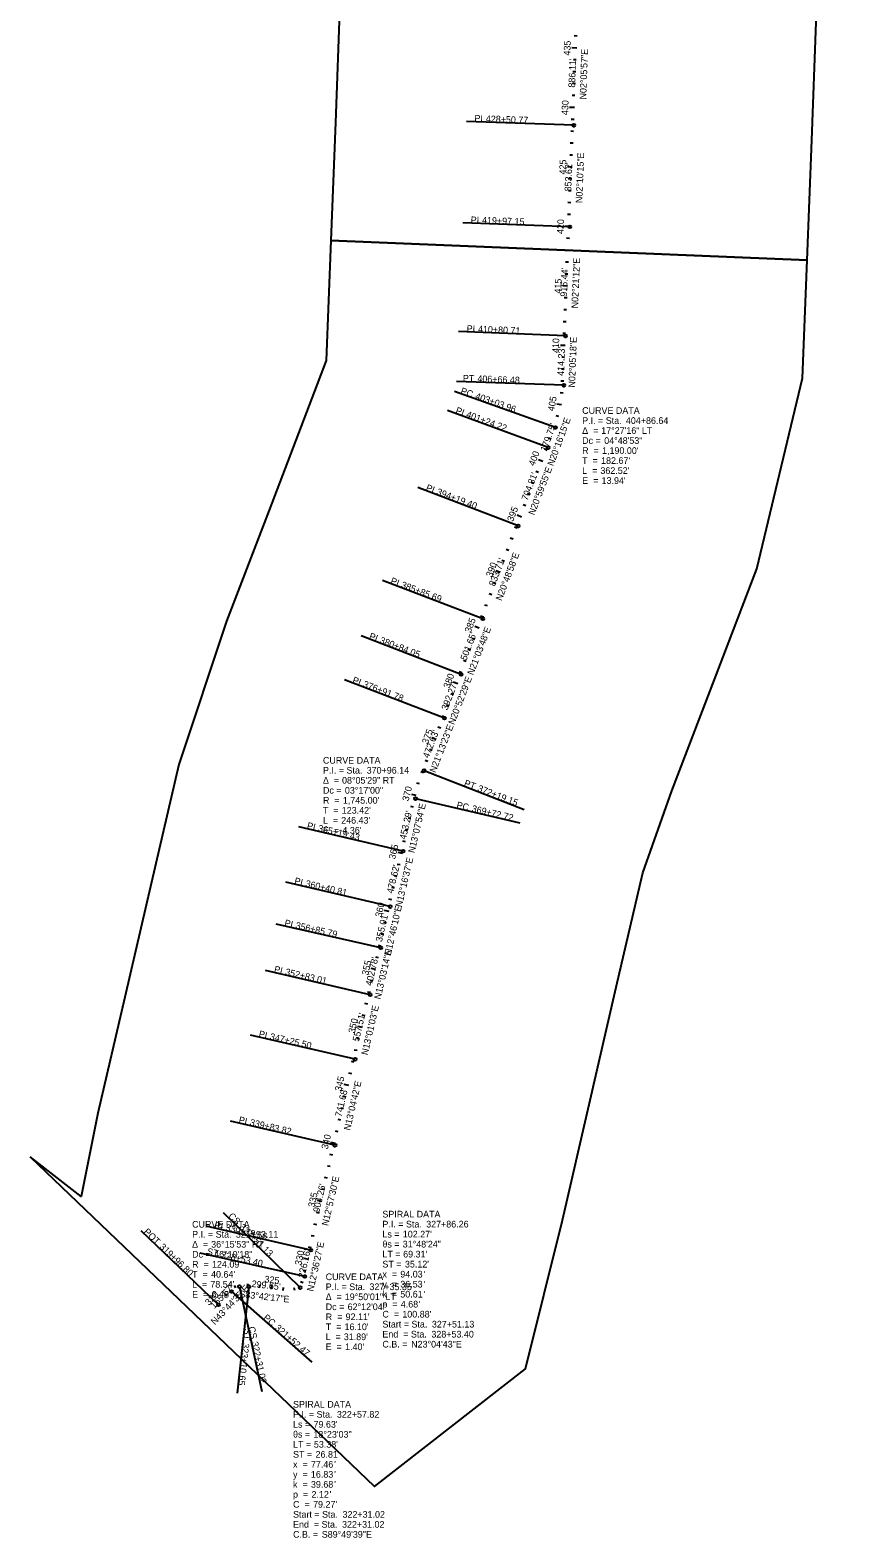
# Model space of a CAD drawing. Extents: x 1697889 to 1709091, y 242468 to 292801.
# Drawn here: x 1697889 to 1704792, y 242468 to 255128 of the extents above; entities that cross this region are included whole.
import ezdxf

# ---------------------------------------------------------------- set-up
doc = ezdxf.new("R2010")
doc.units = 0
for name, color, linetype in [('RD_P_Cells', 7, 'Continuous'), ('SC_Scratch1', 7, 'Continuous'), ('XS_P_Finished_Grade', 7, 'Continuous'), ('XS_P_Headwall', 7, 'Continuous'), ('XS_P_Pavt_Surface', 7, 'Continuous'), ('XS_P_Shoulder_Layers', 7, 'Continuous')]:
    doc.layers.add(name, color=color, linetype=linetype)

msp = doc.modelspace()

# ---------------------------------------------------------------- linework, layer by layer
at = {"layer": 'SC_Scratch1'}
for points in [[(1700412, 253361), (1704409, 253197), (1704447, 254203), (1704484, 255196), (1704524, 256197), (1704561, 257198), (1704600, 258191), (1704641, 259201), (1704677, 260205), (1704716, 261199), (1704754, 262194), (1704792, 263192), (1700795, 263352), (1700757, 262351), (1700719, 261347), (1700679, 260343), (1700644, 259348), (1700604, 258359), (1700564, 257354), (1700528, 256356), (1700487, 255359), (1700450, 254354)], [(1697889, 245666), (1700779, 242900), (1702046, 243888), (1702355, 245136), (1702580, 246108), (1702807, 247091), (1703031, 248053), (1703274, 248740), (1703632, 249675), (1703987, 250604), (1704369, 252207), (1704409, 253197), (1700412, 253361), (1700372, 252353), (1700252, 252037), (1699894, 251097), (1699537, 250165), (1699136, 248961), (1698906, 247975), (1698683, 247009), (1698457, 246033), (1698316, 245333)]]:
    msp.add_lwpolyline(points, close=True, dxfattribs=at)
at = {"layer": 'XS_P_Finished_Grade'}
for p, q in [((1702451, 254329), (1701551, 254362)), ((1702418, 253476), (1701519, 253510)), ((1702381, 252560), (1701482, 252597)), ((1702298, 251792), (1701450, 252093)), ((1702366, 252146), (1701466, 252179)), ((1702236, 251623), (1701391, 251935)), ((1701983, 250965), (1701143, 251288)), ((1701687, 250186), (1700846, 250506)), ((1701507, 249718), (1700667, 250041)), ((1701367, 249351), (1700526, 249672)), ((1701196, 248910), (1702035, 248585)), ((1701123, 248675), (1701999, 248471)), ((1701020, 248234), (1700143, 248438)), ((1700910, 247768), (1700034, 247975)), ((1700832, 247422), (1699954, 247621)), ((1700741, 247029), (1699864, 247233)), ((1700615, 246486), (1699738, 246689)), ((1700447, 245764), (1699571, 245967)), ((1700155, 244569), (1699511, 245198)), ((1699470, 244425), (1698820, 245047)), ((1700244, 244883), (1699367, 245084)), ((1700195, 244662), (1699317, 244858)), ((1699578, 244537), (1700254, 243944)), ((1699724, 244577), (1699626, 243682)), ((1699645, 244577), (1699834, 243697))]:
    msp.add_line(p, q, dxfattribs=at)
for centre in [(1702451, 254329), (1702418, 253476), (1702381, 252560), (1702366, 252146), (1702298, 251792), (1702236, 251623), (1701983, 250965), (1701687, 250186), (1701507, 249718), (1701367, 249351), (1701196, 248910), (1701123, 248675), (1701020, 248234), (1700910, 247768), (1700832, 247422), (1700741, 247029), (1700615, 246486), (1700447, 245764), (1700244, 244883), (1700195, 244662), (1699578, 244537), (1699645, 244577), (1699724, 244577), (1700155, 244569), (1699470, 244425)]:
    msp.add_circle(centre, 12, dxfattribs=at)
at = {"layer": 'XS_P_Headwall'}
for p, q in [((1702475, 254978), (1702435, 254979)), ((1702478, 255078), (1702454, 255079)), ((1702471, 254878), (1702447, 254879)), ((1702467, 254778), (1702443, 254779)), ((1702464, 254678), (1702440, 254679)), ((1702456, 254478), (1702416, 254480)), ((1702460, 254578), (1702436, 254579)), ((1702453, 254378), (1702429, 254379)), ((1702449, 254278), (1702425, 254279)), ((1702445, 254178), (1702421, 254179)), ((1702437, 253978), (1702397, 253980)), ((1702441, 254078), (1702417, 254079)), ((1702434, 253879), (1702410, 253879)), ((1702430, 253779), (1702406, 253779)), ((1702426, 253679), (1702402, 253680)), ((1702419, 253479), (1702379, 253480)), ((1702422, 253579), (1702398, 253580)), ((1702414, 253379), (1702390, 253380)), ((1702410, 253279), (1702386, 253280)), ((1702402, 253079), (1702378, 253080)), ((1702406, 253179), (1702382, 253180)), ((1702398, 252979), (1702358, 252981)), ((1702394, 252879), (1702370, 252880)), ((1702390, 252779), (1702366, 252780)), ((1702382, 252580), (1702358, 252581)), ((1702386, 252679), (1702362, 252680)), ((1702378, 252480), (1702338, 252481)), ((1702374, 252380), (1702350, 252381)), ((1702371, 252280), (1702347, 252281)), ((1702361, 252080), (1702337, 252082)), ((1702367, 252180), (1702343, 252181)), ((1702348, 251981), (1702309, 251988)), ((1702326, 251883), (1702303, 251890)), ((1702262, 251694), (1702239, 251702)), ((1702297, 251788), (1702274, 251796)), ((1702227, 251600), (1702205, 251609)), ((1702191, 251507), (1702154, 251521)), ((1702119, 251320), (1702097, 251329)), ((1702155, 251414), (1702133, 251422)), ((1702084, 251227), (1702061, 251236)), ((1702012, 251040), (1701975, 251055)), ((1702048, 251134), (1702025, 251142)), ((1701976, 250947), (1701954, 250955)), ((1701941, 250853), (1701918, 250862)), ((1701870, 250666), (1701847, 250675)), ((1701905, 250760), (1701883, 250768)), ((1701834, 250573), (1701797, 250587)), ((1701798, 250480), (1701776, 250488)), ((1701727, 250293), (1701705, 250301)), ((1701763, 250386), (1701741, 250395)), ((1701692, 250199), (1701669, 250208)), ((1701656, 250106), (1701619, 250120)), ((1701584, 249919), (1701562, 249928)), ((1701620, 250012), (1701598, 250021)), ((1701548, 249826), (1701526, 249834)), ((1701512, 249732), (1701490, 249741)), ((1701441, 249546), (1701418, 249554)), ((1701477, 249639), (1701439, 249653)), ((1701405, 249452), (1701383, 249461)), ((1701370, 249359), (1701347, 249367)), ((1701297, 249172), (1701260, 249187)), ((1701334, 249266), (1701311, 249274)), ((1701261, 249079), (1701239, 249088)), ((1701189, 248893), (1701166, 248901)), ((1701225, 248986), (1701203, 248995)), ((1701156, 248798), (1701133, 248805)), ((1701129, 248702), (1701091, 248711)), ((1701106, 248604), (1701083, 248610)), ((1701061, 248410), (1701038, 248415)), ((1701084, 248507), (1701060, 248512)), ((1701038, 248312), (1701015, 248318)), ((1701015, 248215), (1700977, 248224)), ((1700970, 248020), (1700946, 248026)), ((1700993, 248118), (1700969, 248123)), ((1700947, 247923), (1700923, 247928)), ((1700924, 247826), (1700900, 247831)), ((1700879, 247631), (1700855, 247636)), ((1700901, 247728), (1700862, 247737)), ((1700857, 247533), (1700833, 247538)), ((1700835, 247436), (1700811, 247441)), ((1700812, 247338), (1700789, 247344)), ((1700767, 247143), (1700744, 247149)), ((1700790, 247241), (1700751, 247250)), ((1700744, 247046), (1700721, 247051)), ((1700722, 246948), (1700698, 246954)), ((1700677, 246754), (1700638, 246763)), ((1700699, 246851), (1700676, 246856)), ((1700654, 246656), (1700631, 246662)), ((1700632, 246559), (1700608, 246564)), ((1700587, 246364), (1700563, 246369)), ((1700609, 246461), (1700586, 246467)), ((1700564, 246267), (1700525, 246276)), ((1700541, 246169), (1700518, 246175)), ((1700519, 246072), (1700495, 246077)), ((1700473, 245877), (1700450, 245882)), ((1700496, 245974), (1700473, 245980)), ((1700451, 245780), (1700412, 245789)), ((1700428, 245682), (1700405, 245687)), ((1700384, 245487), (1700360, 245493)), ((1700406, 245585), (1700383, 245590)), ((1700361, 245390), (1700338, 245395)), ((1700339, 245292), (1700300, 245301)), ((1700294, 245097), (1700270, 245103)), ((1700316, 245195), (1700293, 245200)), ((1700271, 245000), (1700248, 245005)), ((1700249, 244902), (1700226, 244908)), ((1700227, 244805), (1700188, 244814)), ((1699714, 244578), (1699716, 244602)), ((1699913, 244556), (1699917, 244596)), ((1700181, 244610), (1700158, 244619)), ((1700205, 244707), (1700182, 244713)), ((1699542, 244500), (1699524, 244516)), ((1699615, 244566), (1699604, 244588)), ((1699813, 244567), (1699816, 244591)), ((1700012, 244545), (1700015, 244569)), ((1700111, 244544), (1700105, 244567)), ((1699472, 244427), (1699444, 244455))]:
    msp.add_line(p, q, dxfattribs=at)

# ---------------------------------------------------------------- texts
at = {"layer": 'RD_P_Cells'}
for s, p in [('CURVE DATA', (1702521, 251906)), ('P.I. = Sta. ', (1702521, 251822)), ('404+86.64', (1702888, 251822)), ('Δ  = ', (1702521, 251738)), ('Dc = ', (1702521, 251654)), ('17°27\'16" LT', (1702681, 251738)), ('04°48\'53"', (1702706, 251654)), ('R  = ', (1702521, 251570)), ("1,190.00'", (1702688, 251570)), ('T  = ', (1702521, 251486)), ('L  = ', (1702521, 251402)), ("362.52'", (1702674, 251402)), ("182.67'", (1702680, 251486)), ('E  = ', (1702521, 251318)), ("13.94'", (1702684, 251318)), ('CURVE DATA', (1700346, 248969)), ('P.I. = Sta. ', (1700346, 248885)), ('370+96.14', (1700713, 248885)), ('Δ  = ', (1700346, 248801)), ('Dc = ', (1700346, 248717)), ('08°05\'29" RT', (1700506, 248801)), ('03°17\'00"', (1700530, 248717)), ('R  = ', (1700346, 248633)), ("1,745.00'", (1700513, 248633)), ('T  = ', (1700346, 248549)), ('L  = ', (1700346, 248465)), ("246.43'", (1700499, 248465)), ("123.42'", (1700504, 248549)), ('E  = ', (1700346, 248381)), ("4.36'", (1700509, 248381)), ('CURVE DATA', (1699248, 245073)), ('SPIRAL DATA', (1700845, 245158)), ('P.I. = Sta. ', (1700845, 245074)), ('327+86.26', (1701212, 245074)), ('P.I. = Sta. ', (1699248, 244989)), ('321+93.11', (1699615, 244989)), ('Ls = ', (1700845, 244990)), ("102.27'", (1701016, 244990)), ('Δ  = ', (1699248, 244905)), ('Dc = ', (1699248, 244821)), ('36°15\'53" RT', (1699408, 244905)), ('46°10\'18"', (1699433, 244821)), ('θs = ', (1700845, 244906)), ('LT = ', (1700845, 244822)), ('31°48\'24"', (1701015, 244906)), ("69.31'", (1701019, 244822)), ('R  = ', (1699248, 244737)), ("124.09'", (1699415, 244737)), ('ST = ', (1700845, 244738)), ("35.12'", (1701034, 244738)), ('T  = ', (1699248, 244653)), ('L  = ', (1699248, 244569)), ("78.54'", (1699401, 244569)), ("40.64'", (1699407, 244653)), ('CURVE DATA', (1700369, 244632)), ('P.I. = Sta. ', (1700369, 244548)), ('327+35.35', (1700736, 244548)), ('y  = ', (1700845, 244570)), ('x  = ', (1700845, 244654)), ('94.03', (1700995, 244654)), ('36.53', (1700995, 244570)), ("'", (1701190, 244654)), ("'", (1701190, 244570)), ('E  = ', (1699248, 244485)), ("6.48'", (1699411, 244485)), ('Δ  = ', (1700369, 244464)), ('19°50\'01" LT', (1700529, 244464)), ('k  = ', (1700845, 244486)), ('50.61', (1700995, 244486)), ("'", (1701190, 244486)), ('Dc = ', (1700369, 244380)), ('R  = ', (1700369, 244296)), ("92.11'", (1700536, 244296)), ('62°12\'04"', (1700553, 244380)), ('C  = ', (1700845, 244318)), ('p  = ', (1700845, 244402)), ('4.68', (1700999, 244402)), ("100.88'", (1701012, 244318)), ("'", (1701151, 244402)), ('T  = ', (1700369, 244212)), ("16.10'", (1700527, 244212)), ('Start = Sta. ', (1700845, 244234)), ('327+51.13', (1701260, 244234)), ('L  = ', (1700369, 244128)), ('E  = ', (1700369, 244044)), ("31.89'", (1700521, 244128)), ("1.40'", (1700532, 244044)), ('C.B. = ', (1700845, 244066)), ('End  = Sta. ', (1700845, 244150)), ('N23°04\'43"E', (1701086, 244066)), ('328+53.40', (1701256, 244150)), ('SPIRAL DATA', (1700095, 243561)), ('P.I. = Sta. ', (1700095, 243477)), ('322+57.82', (1700463, 243477)), ('θs = ', (1700095, 243309)), ('Ls = ', (1700095, 243393)), ("79.63'", (1700267, 243393)), ('18°23\'03"', (1700266, 243309)), ('LT = ', (1700095, 243225)), ("53.38'", (1700270, 243225)), ('x  = ', (1700095, 243057)), ('ST = ', (1700095, 243141)), ('77.46', (1700245, 243057)), ("26.81'", (1700284, 243141)), ("'", (1700441, 243057)), ('y  = ', (1700095, 242973)), ('16.83', (1700245, 242973)), ("'", (1700441, 242973)), ('k  = ', (1700095, 242889)), ('p  = ', (1700095, 242805)), ('39.68', (1700245, 242889)), ('2.12', (1700250, 242805)), ("'", (1700402, 242805)), ("'", (1700441, 242889)), ('C  = ', (1700095, 242721)), ("79.27'", (1700263, 242721)), ('Start = Sta. ', (1700095, 242637)), ('End  = Sta. ', (1700095, 242553)), ('322+31.02', (1700506, 242553)), ('322+31.02', (1700510, 242637)), ('C.B. = ', (1700095, 242469)), ('S89°49\'39"E', (1700336, 242469))]:
    msp.add_text(s, height=56, dxfattribs=at).set_placement(p)
at = {"layer": 'XS_P_Finished_Grade'}
for s, rotation, p in [('PI', 357.9007, (1701616, 254360)), ('428+50.77', 357.9007, (1701712, 254357)), ('PI', 357.8292, (1701585, 253508)), ('419+97.15', 357.8292, (1701680, 253505)), ('PI', 357.6465, (1701551, 252595)), ('410+80.71', 357.6465, (1701646, 252591)), ('PT', 357.9116, (1701519, 252178)), ('406+66.48', 357.9116, (1701641, 252174)), ('PC', 340.4571, (1701496, 252077)), ('403+03.96', 340.4571, (1701619, 252034)), ('PI', 339.7292, (1701454, 251913)), ('401+24.22', 339.7292, (1701543, 251880)), ('PI', 339.0014, (1701205, 251265)), ('394+19.40', 339.0014, (1701294, 251231)), ('PI', 339.184, (1700908, 250483)), ('385+85.69', 339.184, (1700997, 250449)), ('PI', 338.9367, (1700728, 250018)), ('380+84.05', 338.9367, (1700817, 249984)), ('PI', 339.1253, (1700588, 249649)), ('376+91.78', 339.1253, (1700677, 249615)), ('PT', 338.777, (1701525, 248784)), ('372+19.15', 338.777, (1701638, 248740)), ('PC', 346.8683, (1701463, 248597)), ('369+72.72', 346.8683, (1701590, 248567)), ('PI', 346.8683, (1700208, 248424)), ('365+19.43', 346.8683, (1700301, 248402)), ('PI', 346.7231, (1700102, 247960)), ('360+40.81', 346.7231, (1700195, 247938)), ('PI', 347.2306, (1700019, 247607)), ('356+85.79', 347.2306, (1700112, 247586)), ('PI', 346.9462, (1699932, 247218)), ('352+83.01', 346.9462, (1700025, 247196)), ('PI', 346.9824, (1699803, 246675)), ('347+25.50', 346.9824, (1699896, 246653)), ('PI', 346.9216, (1699635, 245953)), ('339+83.82', 346.9216, (1699728, 245932)), ('PI', 347.0418, (1699432, 245070)), ('CS', 315.689, (1699547, 245164)), ('327+51.13', 315.689, (1699640, 245073)), ('POT', 316.2569, (1698837, 245032)), ('330+79.56', 347.0418, (1699525, 245049)), ('319+96.80', 316.2569, (1698969, 244906)), ('ST', 347.3926, (1699369, 244848)), ('328+53.40', 347.3926, (1699487, 244821)), ('PC', 318.7374, (1699840, 244309)), ('ST', 263.7047, (1699687, 244226)), ('CS', 282.0888, (1699719, 244236)), ('321+52.47', 318.7374, (1699938, 244223)), ('323+10.65', 263.7047, (1699673, 244105)), ('322+31.02', 282.0888, (1699746, 244109))]:
    msp.add_text(s, height=56, rotation=rotation, dxfattribs=at).set_placement(p)
at = {"layer": 'XS_P_Headwall'}
for s, rotation, p in [('435', 87.9007, (1702421, 254914)), ('430', 87.9007, (1702403, 254414)), ('425', 87.8292, (1702384, 253915)), ('420', 87.8292, (1702365, 253415)), ('415', 87.6465, (1702344, 252915)), ('410', 87.9116, (1702325, 252416)), ('405', 79.8958, (1702286, 251925)), ('400', 69.0014, (1702120, 251464)), ('395', 69.0014, (1701941, 250997)), ('390', 69.184, (1701763, 250530)), ('385', 68.9367, (1701585, 250063)), ('380', 69.1253, (1701406, 249596)), ('375', 68.777, (1701226, 249129)), ('370', 75.9726, (1701064, 248650)), ('365', 76.7231, (1700951, 248162)), ('360', 77.2306, (1700837, 247675)), ('355', 76.9462, (1700725, 247188)), ('350', 76.9824, (1700612, 246701)), ('345', 76.9216, (1700499, 246214)), ('340', 76.9216, (1700386, 245727)), ('335', 77.0418, (1700274, 245239)), ('330', 77.3926, (1700163, 244752)), ('325', 353.7047, (1699853, 244614)), ('320', 46.2569, (1699390, 244415))]:
    msp.add_text(s, height=56, rotation=rotation, dxfattribs=at).set_placement(p)
at = {"layer": 'XS_P_Pavt_Surface'}
for s, rotation, p in [('N02°05\'57"E', 87.9007, (1702555, 254545)), ('N02°10\'15"E', 87.8292, (1702522, 253675)), ('N02°21\'12"E', 87.6465, (1702486, 252791)), ('N02°05\'18"E', 87.9116, (1702461, 252126)), ('N20°16\'15"E', 69.7292, (1702279, 251464)), ('N20°59\'55"E', 69.0014, (1702119, 251051)), ('N20°48\'58"E', 69.184, (1701845, 250332)), ('N21°03\'48"E', 68.9367, (1701606, 249708)), ('N20°52\'29"E', 69.1253, (1701447, 249291)), ('N21°13\'23"E', 68.777, (1701290, 248888)), ('N13°07\'54"E', 76.8683, (1701114, 248215)), ('N13°16\'37"E', 76.7231, (1701007, 247761)), ('N12°46\'10"E', 77.2306, (1700915, 247356)), ('N13°03\'14"E', 76.9462, (1700829, 246986)), ('N13°01\'03"E', 76.9824, (1700721, 246518)), ('N13°04\'42"E', 76.9216, (1700574, 245885)), ('N12°57\'30"E', 77.0418, (1700389, 245084)), ('N12°36\'27"E', 77.3926, (1700265, 244533)), ('N43°44\'35"E', 46.2569, (1699439, 244253)), ('S83°42\'17"E', 353.7047, (1699643, 244489))]:
    msp.add_text(s, height=56, rotation=rotation, dxfattribs=at).set_placement(p)
at = {"layer": 'XS_P_Shoulder_Layers'}
for s, rotation, p in [("886.11'", 87.9007, (1702461, 254645)), ("853.62'", 87.8292, (1702429, 253773)), ("916.44'", 87.6465, (1702393, 252889)), ("414.23'", 87.9116, (1702368, 252224)), ("179.75'", 69.7292, (1702221, 251586)), ("704.81'", 69.0014, (1702062, 251173)), ("833.71'", 69.184, (1701788, 250454)), ("501.65'", 68.9367, (1701549, 249831)), ("392.27'", 69.1253, (1701390, 249413)), ("472.63'", 68.777, (1701233, 249010)), ("453.29'", 76.8683, (1701041, 248328)), ("478.62'", 76.7231, (1700934, 247875)), ("355.01'", 77.2306, (1700841, 247469)), ("402.78'", 76.9462, (1700756, 247099)), ("557.51'", 76.9824, (1700648, 246632)), ("741.68'", 76.9216, (1700501, 245999)), ("904.26'", 77.0418, (1700316, 245197)), ("226.16'", 77.3926, (1700190, 244646)), ("155.67'", 46.2569, (1699434, 244388)), ("299.65'", 353.7047, (1699745, 244575))]:
    msp.add_text(s, height=56, rotation=rotation, dxfattribs=at).set_placement(p)

doc.saveas('drawing.dxf')
